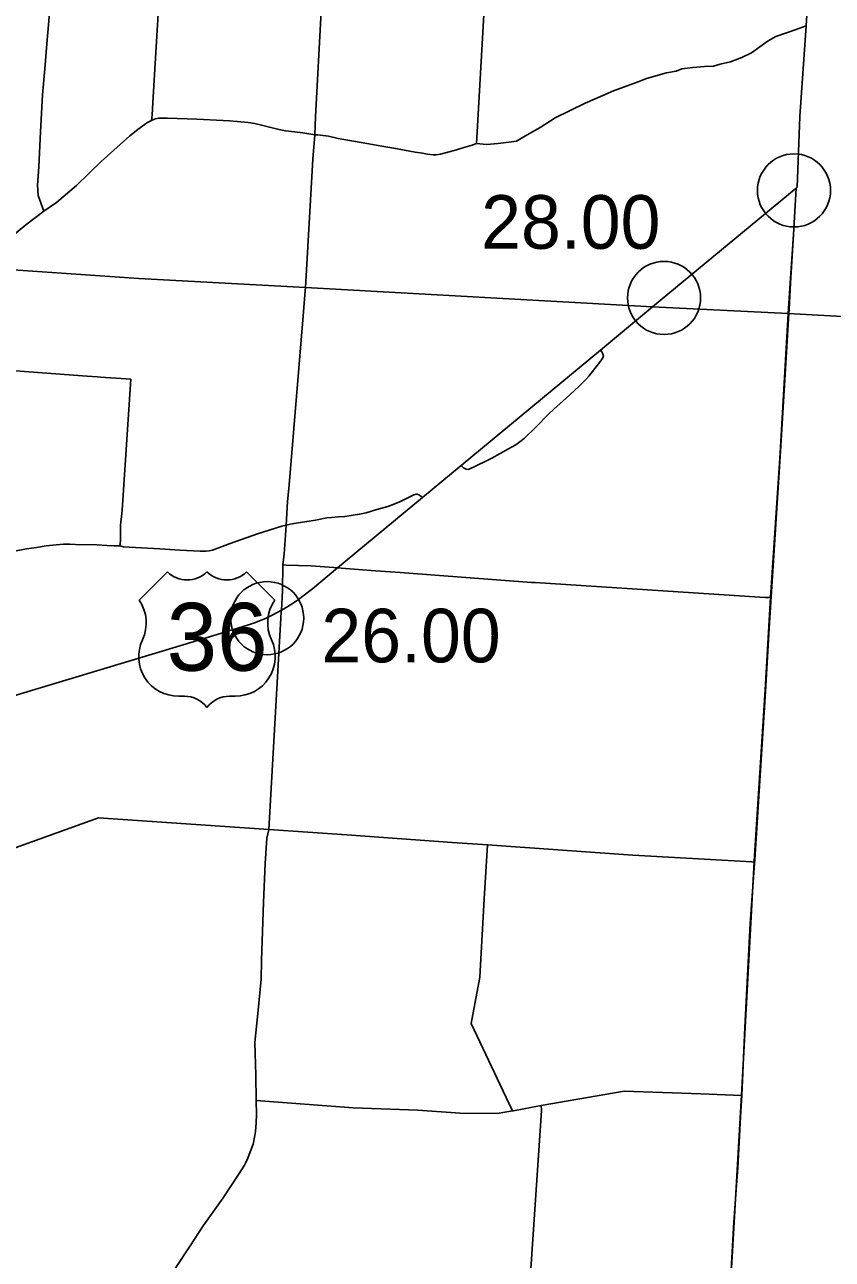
# Model space of a CAD drawing. Extents: x 1597222 to 1925846, y 496284 to 911751.
# Drawn here: x 1882846 to 1899422, y 810051 to 835395 of the extents above; entities that cross this region are included whole.
import ezdxf

# ---------------------------------------------------------------- set-up
doc = ezdxf.new("R2010")
doc.units = 0
for name, color, linetype in [('Default', 7, 'Continuous'), ('GM_X_Adjacent_County', 7, 'Continuous'), ('GM_X_County', 7, 'Continuous'), ('GM_X_County_Road', 7, 'Continuous'), ('GM_X_Township', 7, 'Continuous'), ('GM_X_Township_Road', 7, 'Continuous'), ('GM_X_US_Route', 7, 'Continuous'), ('GM_X_US_Shield', 7, 'Continuous')]:
    doc.layers.add(name, color=color, linetype=linetype)

msp = doc.modelspace()

# ---------------------------------------------------------------- linework, layer by layer
at = {"layer": 'Default'}
for centre in [(1898635, 831992), (1895968, 829786), (1887823, 823212)]:
    msp.add_circle(centre, 750, dxfattribs=at)
at = {"layer": 'GM_X_Adjacent_County'}
msp.add_line((1898513, 829466), (1915254, 828516), dxfattribs=at)
at = {"layer": 'GM_X_County'}
msp.add_lwpolyline([(1899202, 840435), (1898887, 835373), (1898754, 833509), (1898698, 832056), (1898677, 832037), (1898625, 831088), (1898557, 830092), (1898513, 829466), (1898352, 826597), (1898155, 823638), (1898045, 821739), (1897825, 818330), (1897815, 818218), (1897557, 813421), (1897406, 810815), (1897032, 804371)], dxfattribs=at)
at = {"layer": 'GM_X_County_Road'}
for points in [[(1888604, 829939), (1888609, 830001), (1888760, 832637), (1888800, 833137), (1888812, 833505), (1889049, 837835), (1889053, 837918), (1889133, 839176), (1889247, 841285), (1889264, 841582), (1889332, 842735), (1889339, 842955), (1889347, 843044), (1889371, 843177), (1889414, 843329), (1889428, 843400), (1889436, 843472), (1889534, 844778), (1889539, 844855)], [(1883240, 831567), (1883121, 831886), (1883110, 832097), (1883136, 832477), (1883174, 833194), (1883211, 833953), (1883259, 834488), (1883303, 835001), (1883338, 835393), (1883351, 835566), (1883352, 835653)], [(1883240, 831567), (1883496, 831745), (1883911, 832096), (1884413, 832583), (1884807, 832938), (1885003, 833112), (1885166, 833243), (1885326, 833358), (1885368, 833385), (1885446, 833427), (1885524, 833460), (1885556, 833468), (1885599, 833476), (1885624, 833478), (1885649, 833478), (1885778, 833475), (1886380, 833452), (1886918, 833430), (1887051, 833421), (1887207, 833409), (1887432, 833384), (1887568, 833364), (1887708, 833334), (1887981, 833265), (1888133, 833232), (1888203, 833219), (1888385, 833194), (1888553, 833173), (1888800, 833137), (1888866, 833133), (1889085, 833106), (1889281, 833061), (1889870, 832955), (1890175, 832901), (1890421, 832859), (1890857, 832781), (1891011, 832754), (1891116, 832738), (1891228, 832726), (1891289, 832726), (1891379, 832736), (1891557, 832782), (1891660, 832813), (1891907, 832887), (1892010, 832918), (1892122, 832957), (1892327, 832934), (1892566, 832957), (1892784, 832982), (1892937, 833003), (1893157, 833131), (1893427, 833287), (1893731, 833483), (1894025, 833628), (1894350, 833781), (1894712, 833939), (1894934, 834036), (1895214, 834140), (1895437, 834225), (1895608, 834291), (1896021, 834405), (1896215, 834443), (1896330, 834491), (1896557, 834514), (1896797, 834537), (1896986, 834540), (1897122, 834582), (1897333, 834631), (1897563, 834720), (1897761, 834818), (1898107, 835064), (1898263, 835149), (1898656, 835291), (1898887, 835373)], [(1898531, 829465), (1898535, 829554), (1898563, 830092), (1898625, 831088), (1898677, 832037)], [(1881648, 830290), (1881808, 830417), (1882869, 831288), (1883240, 831567)], [(1888211, 825123), (1888238, 825608), (1888269, 825875), (1888275, 825951), (1888566, 829499), (1888604, 829939)], [(1897822, 818179), (1897829, 818255), (1897948, 820090), (1898048, 821704), (1898128, 823007), (1898166, 823650), (1898353, 826531), (1898388, 827089), (1898531, 829465)], [(1891807, 826349), (1891855, 826296), (1891892, 826275), (1891910, 826271), (1891947, 826267), (1891967, 826270), (1892112, 826338), (1892322, 826440), (1892434, 826497), (1892779, 826687), (1892926, 826772), (1893037, 826849), (1893103, 826910), (1893327, 827129), (1893595, 827398), (1893703, 827499), (1893960, 827731), (1894216, 827965), (1894365, 828110), (1894427, 828179), (1894548, 828334), (1894670, 828497), (1894687, 828515), (1894710, 828555), (1894718, 828575), (1894723, 828595), (1894722, 828618), (1894713, 828640), (1894693, 828679), (1894662, 828715)], [(1882637, 824590), (1882881, 824632), (1883086, 824662), (1883290, 824696), (1883493, 824720), (1883640, 824734), (1883773, 824733), (1883887, 824727), (1884332, 824715), (1884531, 824707), (1884682, 824698), (1884802, 824698), (1884869, 824677), (1885617, 824633), (1886029, 824607), (1886447, 824588), (1886561, 824584), (1886629, 824591), (1886701, 824609), (1887064, 824744), (1887621, 824941), (1888121, 825102), (1888211, 825123), (1888301, 825141), (1888421, 825162), (1888813, 825227), (1889047, 825270), (1889140, 825279), (1889289, 825293), (1889417, 825300), (1889589, 825323), (1889719, 825344), (1889858, 825376), (1890073, 825441), (1890297, 825503), (1890440, 825558), (1890572, 825616), (1890734, 825693), (1890836, 825744), (1890880, 825758), (1890902, 825760), (1890937, 825746), (1890980, 825715), (1891009, 825686)], [(1888119, 823374), (1888136, 823770), (1888147, 824305), (1888170, 824530), (1888198, 824915), (1888211, 825123)], [(1888147, 824305), (1888213, 824298), (1888717, 824283), (1889192, 824249), (1889265, 824243)], [(1889265, 824243), (1889344, 824238), (1890044, 824187), (1890551, 824150), (1893249, 823947), (1893321, 823942), (1897937, 823643), (1898048, 823639), (1898076, 823638), (1898114, 823638), (1898140, 823641), (1898166, 823650)], [(1885938, 809865), (1886242, 810330), (1886511, 810739), (1886917, 811312), (1887249, 811810), (1887355, 811986), (1887375, 812027), (1887424, 812129), (1887477, 812258), (1887533, 812417), (1887573, 812593), (1887586, 812678), (1887600, 812854), (1887602, 813023), (1887597, 813309), (1887587, 813833), (1887573, 814503), (1887636, 815166), (1887701, 815803), (1887705, 816183), (1887748, 817374), (1887780, 818173), (1887818, 818696), (1887858, 818871), (1888113, 823336), (1888119, 823374)], [(1871277, 818480), (1872206, 818406), (1875525, 818156), (1880663, 817814), (1881619, 818131), (1884362, 819111), (1887858, 818871), (1889457, 818761), (1891623, 818604), (1892346, 818560), (1895326, 818344), (1897532, 818224), (1897769, 818211), (1897801, 818204), (1897822, 818179)], [(1897564, 813416), (1897624, 814812), (1897737, 816947), (1897822, 818179)], [(1896877, 801685), (1896878, 801713), (1896961, 803039), (1897015, 803890), (1897038, 804349), (1897401, 810812), (1897452, 811576), (1897482, 811930), (1897540, 812982), (1897564, 813416)]]:
    msp.add_lwpolyline(points, dxfattribs=at)
at = {"layer": 'GM_X_Township'}
msp.add_lwpolyline([(1870309, 808163), (1870779, 814239), (1870903, 816053), (1870933, 816495), (1870943, 816996), (1871003, 817857), (1871065, 818497), (1871124, 819057), (1871199, 820179), (1871965, 831096), (1873866, 830983), (1874715, 830911), (1874782, 830900), (1876113, 830808), (1881808, 830417), (1885186, 830186), (1888609, 830001), (1895732, 829600), (1898513, 829466)], dxfattribs=at)
at = {"layer": 'GM_X_Township_Road'}
for points in [[(1892122, 832957), (1892339, 836806), (1892341, 836860), (1892582, 840972), (1892585, 841036), (1892586, 841074), (1892651, 842825), (1892652, 842854), (1892658, 842912), (1892664, 842941), (1892680, 842997), (1892719, 843085), (1892728, 843106), (1892742, 843149), (1892749, 843194), (1892750, 843216), (1892770, 843468), (1892794, 843834), (1892869, 844984), (1892893, 845346)], [(1885446, 833427), (1885462, 833535), (1885473, 833796), (1885574, 835394), (1885580, 835487), (1885580, 835490), (1885581, 835505), (1885831, 839707), (1885835, 839776), (1885999, 842676), (1886002, 842745), (1886125, 844378), (1886129, 844439)], [(1880432, 828452), (1880452, 828445), (1880516, 828438), (1880549, 828431), (1880745, 828411), (1881545, 828362), (1882567, 828296), (1884124, 828178)], [(1884124, 828178), (1884130, 828177), (1884339, 828164), (1884399, 828160), (1884926, 828125), (1885023, 828118), (1884844, 825432), (1884839, 825362), (1884813, 825123), (1884810, 824800), (1884802, 824698)], [(1892877, 813100), (1892856, 813096), (1892847, 813127), (1892013, 814894), (1892187, 815844), (1892275, 817450), (1892346, 818560)], [(1887597, 813309), (1889585, 813162), (1890912, 813114), (1891786, 813054), (1892545, 813045), (1892856, 813096)], [(1893446, 813209), (1895152, 813500), (1896723, 813446), (1897564, 813416)], [(1891373, 803023), (1891387, 803039), (1891405, 803057), (1892171, 803626), (1892889, 804151), (1893142, 808538), (1893444, 812998), (1893450, 813114), (1893446, 813209)], [(1893446, 813209), (1892877, 813100)]]:
    msp.add_lwpolyline(points, dxfattribs=at)
at = {"layer": 'GM_X_US_Route'}
msp.add_lwpolyline([(1880687, 821035), (1883192, 821790), (1886098, 822667), (1886884, 822903), (1887402, 823063), (1887564, 823117), (1887787, 823203), (1887941, 823279), (1888119, 823374), (1888248, 823452), (1888302, 823484), (1888354, 823517), (1888407, 823552), (1888458, 823588), (1888528, 823642), (1888751, 823815), (1889265, 824243), (1891009, 825686), (1891807, 826349), (1894662, 828715), (1895732, 829600), (1898677, 832037), (1898698, 832056)], dxfattribs=at)
at = {"layer": 'GM_X_US_Shield'}
for p, q in [((1885775, 824163), (1885195, 823583)), ((1885775, 824163), (1885195, 823583)), ((1887980, 823583), (1887400, 824163)), ((1887980, 823583), (1887400, 824163)), ((1886007, 821611), (1886123, 821611)), ((1886007, 821611), (1886123, 821611)), ((1887051, 821611), (1887167, 821611)), ((1887051, 821611), (1887167, 821611))]:
    msp.add_line(p, q, dxfattribs=at)
for centre, radius, start, end in [((1886181, 824577), 580, 225.573, 314.427), ((1886181, 824577), 580, 225.573, 314.427), ((1886993, 824577), 580, 225.573, 314.427), ((1886993, 824577), 580, 225.573, 314.427), ((1884530, 823117), 812, 334.5471, 35.0009), ((1884530, 823117), 812, 334.5471, 35.0009), ((1888645, 823117), 812, 144.9991, 205.4529), ((1888645, 823117), 812, 144.9991, 205.4529), ((1885998, 822423), 812, 154.8319, 270.6383), ((1885998, 822423), 812, 154.8319, 270.6383), ((1887177, 822423), 812, 269.3617, 25.1681), ((1887177, 822423), 812, 269.3617, 25.1681), ((1886123, 821030), 580, 36.8699, 90), ((1886123, 821030), 580, 36.8699, 90), ((1887051, 821030), 580, 90, 143.1301), ((1887051, 821030), 580, 90, 143.1301)]:
    msp.add_arc(centre, radius, start, end, dxfattribs=at)

# ---------------------------------------------------------------- texts
at = {"layer": 'Default'}
for s, p in [('28.00', (1892214, 830795)), ('26.00', (1888935, 822305))]:
    msp.add_text(s, height=1100, dxfattribs=at).set_placement(p)
at = {"layer": 'GM_X_US_Shield'}
msp.add_text('36', height=1392.2, dxfattribs=at).set_placement((1885760, 822133))
msp.add_text('36', height=1392.2, dxfattribs=at).set_placement((1885760, 822133))

doc.saveas('drawing.dxf')
